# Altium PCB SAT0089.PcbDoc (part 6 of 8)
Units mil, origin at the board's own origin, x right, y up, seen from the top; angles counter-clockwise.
Board outline 4075 x 2715 mil, 6 copper layers (Top Layer, InternalPlane1, MidLayer1, Internal Plane 3, InternalPlane2, Bottom Layer), stack 67.4 mil thick; 538 components, 405 nets, 1716 pads, 1236 vias.
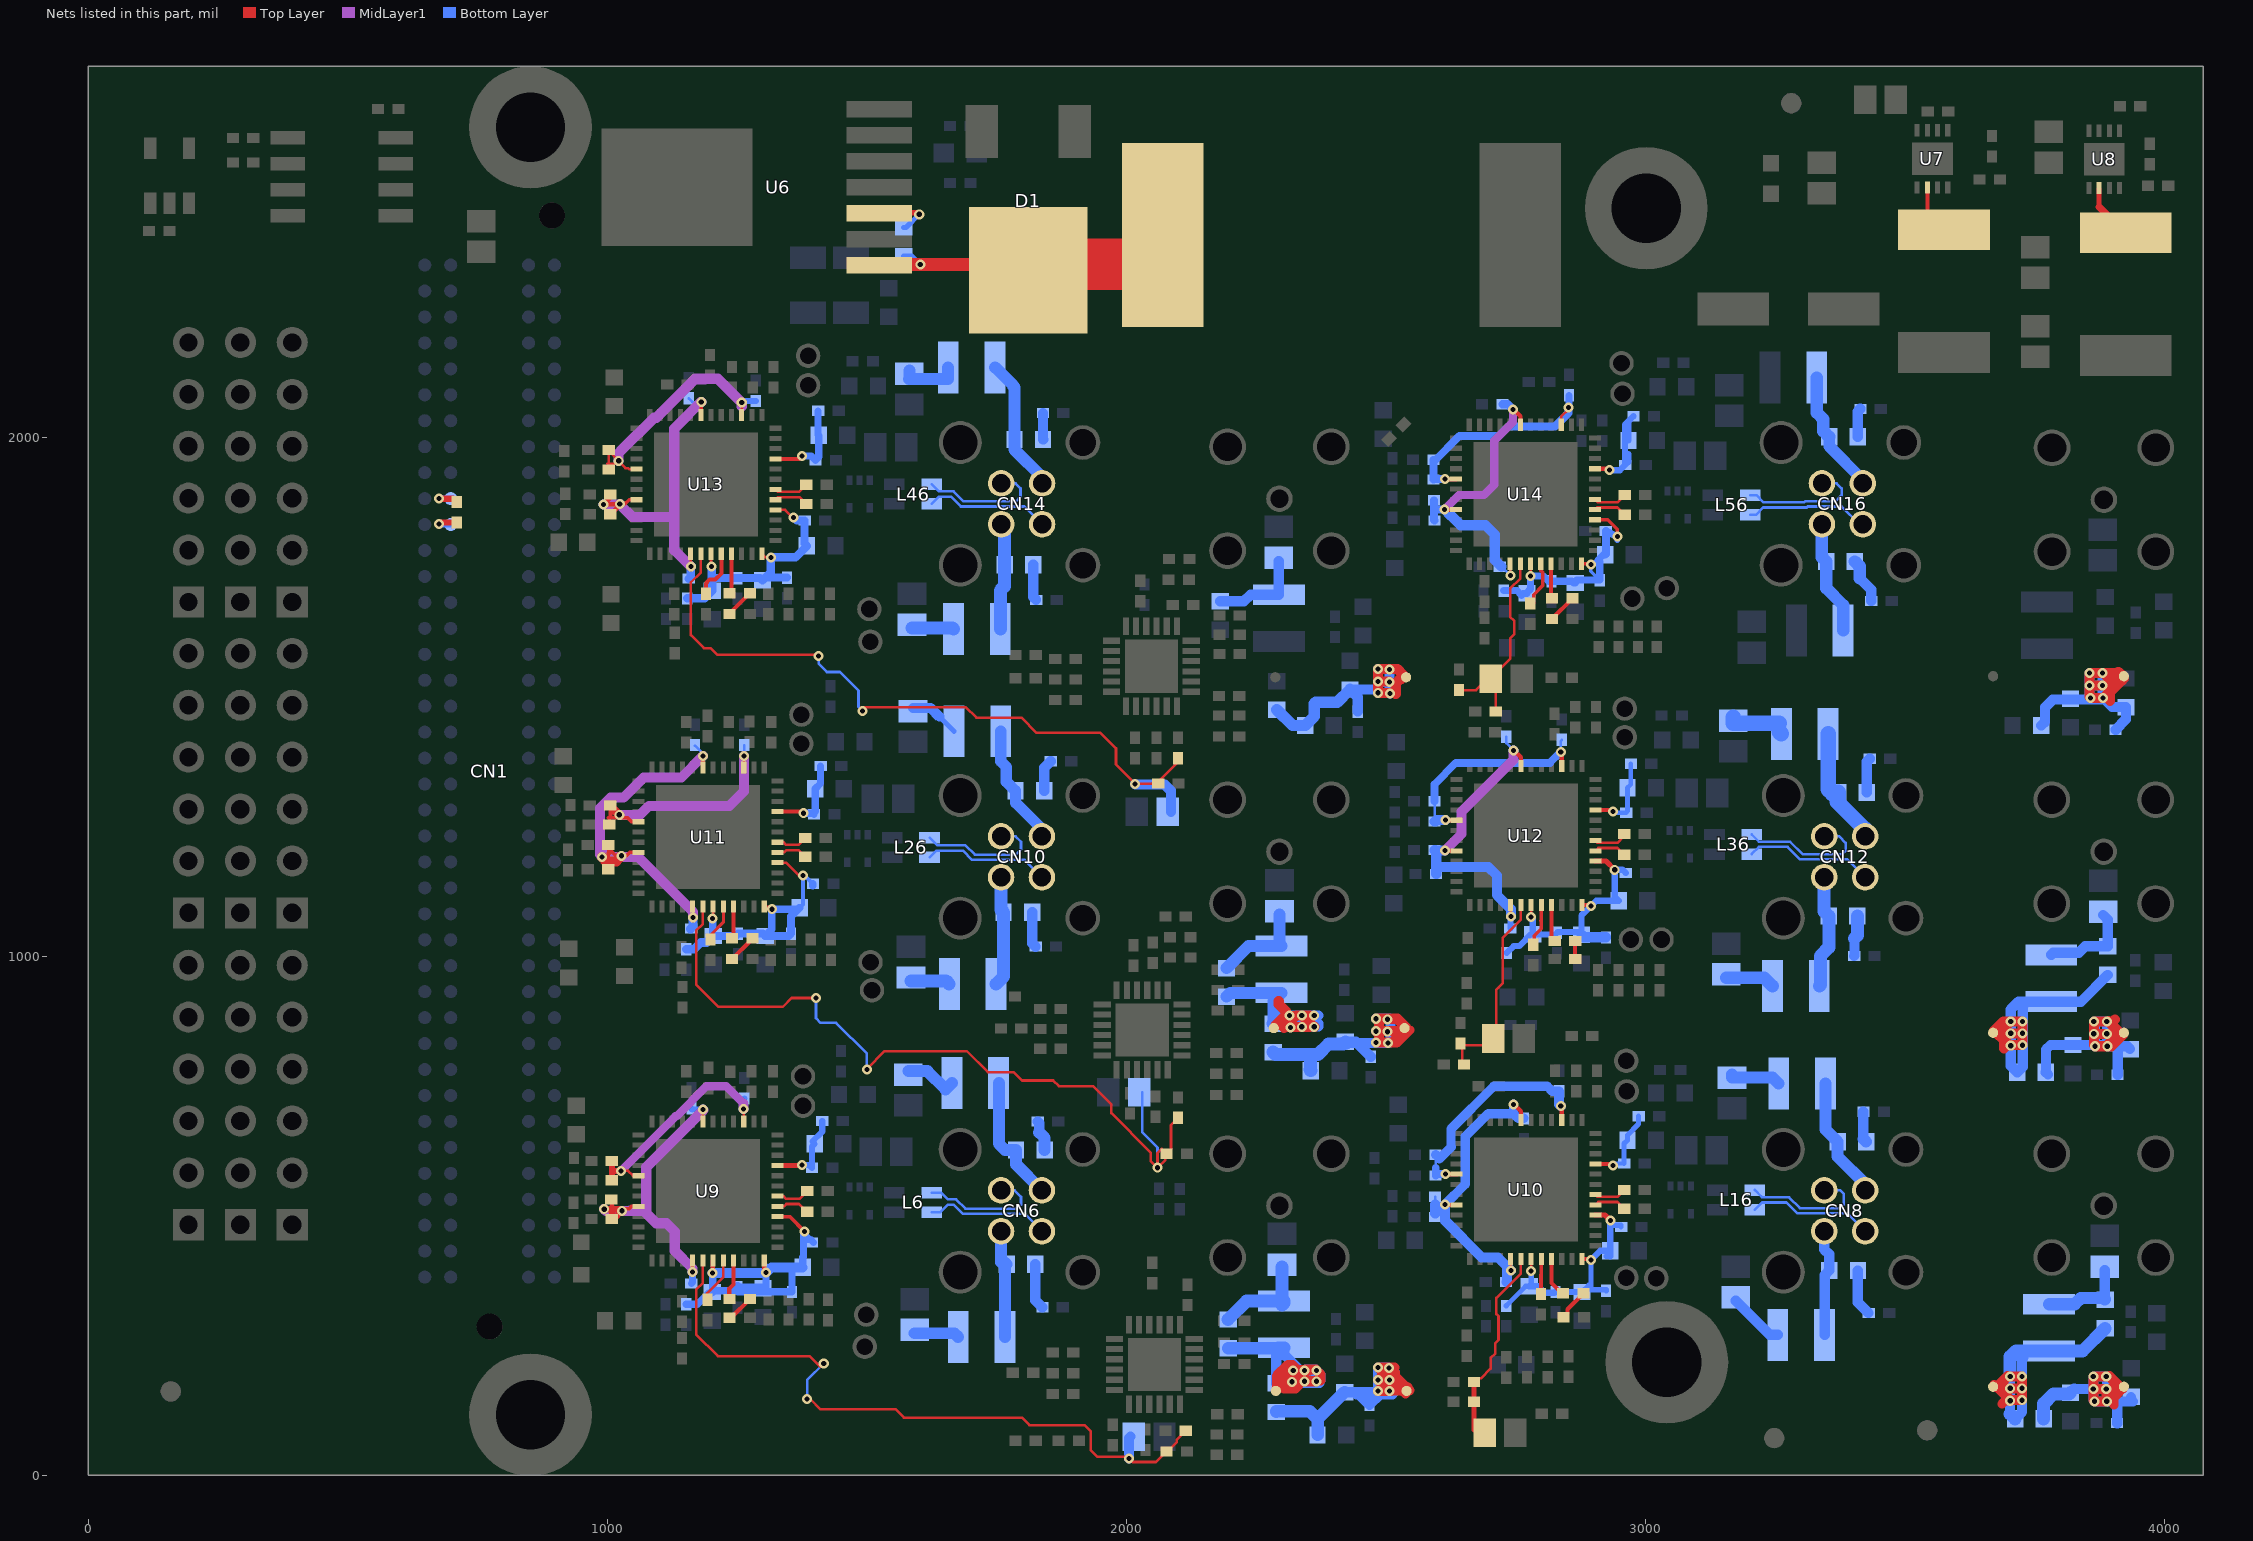
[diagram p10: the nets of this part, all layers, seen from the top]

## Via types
v1: diameter 19.29, hole 9.84, Top Layer to Bottom Layer, tented both sides, 1155 vias
v2: diameter 19.68, hole 7.87, Top Layer to Bottom Layer, tented both sides, 80 vias
v3: diameter 22, hole 10, Top Layer to Bottom Layer, tented both sides, 1 vias

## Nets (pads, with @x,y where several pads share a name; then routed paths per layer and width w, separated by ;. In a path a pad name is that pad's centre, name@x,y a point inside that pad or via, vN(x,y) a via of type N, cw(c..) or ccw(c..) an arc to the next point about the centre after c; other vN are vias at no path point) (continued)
NetC10_1: C10.1 U6.3 | length 100.8
  Top Layer w9.84: U6.3@1542,2433 1598,2433 v1(1601,2430)
  Bottom Layer w9.84: C10.1@1571,2404.5 1575.5,2404.5 v1(1601,2430)
NetC10_2: C10.2 D1.4 L1.1 U6.1 | length 590.3
  Top Layer w25: U6.1@1542,2333 v1(1603,2333) 1811.31,2333 D1.4@1812.05,2333.74
  Top Layer w50: L1.1@2013.82,2333.74 L1.1@2069.92,2389.84
  Top Layer w100: D1.4@1812.05,2333.74 L1.1@2013.82,2333.74
  Bottom Layer w9.84: C10.2@1571,2349.5 1586.5,2349.5 v1(1603,2333)
NetC16_1: C16.1 C17.1 L7.1 L9.2 R27.2 | length 900.3
  Top Layer w17.72: v1@2510,163 2533.08,163 2534.08,163 2535.11,163 L9.2@2539.98,163 2544.95,163 L9.2@2546.02,164.06
  Top Layer w19.29: v1@2498,184 2497,184 ; v1(2507,184) 2516,175 2519,175 ; v1@2510,163 v1(2507,163) ; 2517,208 v1@2507,208 ; 2519,184 2519,175 ; L9.2@2533.08,163 L9.2@2538.02,158.06 ; L9.2@2534.08,163 L9.2@2538.02,159.06 ; L9.2@2540.11,168 2518,190.11 2518,198 2515,198 v1(2506,207) ; v1(2485,184) 2494,175 2497,175 ; v1(2485,184) 2497,184 ; v1(2485,184) 2496,195 2497,195 ; 2497,175 2497,174 2496,174 v1(2485,163) v1(2507,163) ; 2497,175 2497,184 ; 2497,184 2497,195 ; 2497,195 2497,199 2494,199 v1(2485,208) v1@2506,208 ; v1(2506,207) v1@2506,208 ; v1(2506,207) v1@2507,208 ; v1@2506,208 v1@2507,208 ; v1(2507,163) 2518,174 2519,174 2519,175
  Top Layer w24: L9.2@2535.11,163 L9.2@2540.11,168
  Bottom Layer w19.29: 2464.5,160.5 v1@2487,160.5 ; 2497,156 2492,156 v1@2487.5,160.5 ; 2497,175 2494,175 v1(2485,184) ; 2497,195 2496,195 v1(2485,184) ; v1(2507,184) 2518,184 ; 2516.5,160.5 2512,160.5 v1@2509.5,160.5 ; v1(2485,184) v1(2485,163) v1@2487,161 ; v1(2485,184) v1(2485,208) 2505,208 v1(2506,207) 2515,198 2518,198 2518,184 ; v1@2487,160.5 v1@2487,161 ; v1@2487,160.5 v1@2487.5,160.5 ; v1@2487,161 v1@2487.5,160.5 ; v1@2487.5,160.5 v1@2509.5,160.5 ; v1@2509.5,160.5 2509,161 v1(2507,163) 2508,164 2518,164 2518,184
  Bottom Layer w20: L7.1@2421,160.5 2464.5,160.5 C16.1@2464.5,140 ; 2443.5,156 2448.5,156 C16.1@2464.5,140 ; 2492,156 2488.5,156 2468.5,136 C16.1@2464.5,140 ; 2497,156 2512,156 2512,160.5 2512,161 v1@2509,161
  Bottom Layer w24: R27.2@2289,122.5 2289,123.5 2353.5,123.5 2368.5,108.5 ; C17.1@2368.5,78 2368.5,108.5 ; L7.1@2421,160.5 2420.5,160.5 2368.5,108.5
NetC20_1: C20.1 CN6.3 L4.1 | length 253.4
  Bottom Layer w23: L4.1@1754.28,756 1754.28,639.22 1766.5,627 C20.1@1787.44,627 1787.5,627 1787.5,599.24 CN6.3@1837.37,549.37
NetC20_2: C20.2 R28.2 | length 60.6
  Bottom Layer w20: R28.2@1829,682 1832,679 1832,661
  Bottom Layer w23: 1832,661 1842.5,650.5 C20.2@1842.5,627
NetC21_1: C21.1 CN6.1 L5.1 | length 213.6
  Bottom Layer w23: CN6.1@1758.63,470.63 1758.63,410.87 1765.63,410.87 1769.5,407 1766.28,403.78 L5.1@1766.28,267
NetC21_2: C21.2 R29.2 | length 88.6
  Bottom Layer w20: C21.2@1824.5,407 1824.5,337.5 R29.2@1838,324
NetC23_1: C23.1 U9.41 | length 65.2
  Top Layer w5: U9.41@1327.86,518.47 1340.47,518.47 1345,523 1369,523 1384,508 C23.1@1385,508
NetC24_1: C24.1 U9.42 | length 65.5
  Top Layer w5: U9.42@1327.86,538.16 1339.51,538.16 1344.67,533 1370,533 C24.1@1385,548
NetC25_1: C25.1 U9.32 | length 88.6
  Top Layer w5: C25.1@1193,339 1192,340 1192,351 1223.53,382.53 U9.32@1223.53,414.14
NetC26_1: C26.1 R30.1 | length 53.9
  Top Layer w8: R30.1@1235.32,305 1239.68,305 C26.1@1274.68,340
NetC26_2: C26.2 U9.33 | length 77.7
  Top Layer w8: C26.2@1235.31,340 1235,340.31 1235,360 1243.21,368.21 U9.33@1243.21,414.14
NetC27_1: C27.1 C208.1 L10.1 U9.3 U9.17 | length 484
  Top Layer w5: L10.1@1009,606 1010,605 1010,587 ; v1(1026,587) 1040,587 1049.47,577.53 U9.17@1060.14,577.53 ; v1(1262,706) 1262.9,705.1 U9.3@1262.9,681.86
  Top Layer w11.81: C208.1@1009,569 L10.1@1009,606 ; 1010,587 v1(1026,587)
  MidLayer1 w16: v1(1026,587) 1131,692 1133,692 1191,750 1229,750 1262,717
  MidLayer1 w19.29: v1(1262,706) 1262,717
  Bottom Layer w11.81: v1(1262,706) 1262,724 C27.1@1264,726
NetC30_1: C30.1 C31.1 C32.1 L11.1 U9.7 U9.20 U9.29 | length 730.8
  Top Layer w5: v1(1184,705) 1184,682.02 U9.7@1184.16,681.86
  Top Layer w7.01: C31.1@1009,532 1009,516 1011,514 1042,514 1046.47,518.47 U9.20@1060.14,518.47 ; v1(1164,392) 1164.47,392.47 U9.29@1164.47,414.14
  Top Layer w12: v1(994,513) 1009,513 ; 1009,516 1009,513 ; 1009,513 1025,513 v1(1028,510) 1012,494 1009,494 1009,513
  MidLayer1 w19.29: v1(994,513) 997,510 v1(1028,510) 1044,510 ; 1130,433 1164,399 v1(1164,392) ; v1(1184,705) v1@1185,704
  MidLayer1 w19.68: 1044,510 1070,510 1094,486 1114,486 1130,470 1130,433 ; 1075,510 1075,594 v1@1185,704
  Bottom Layer w11.81: C30.1@1162,707 1164,705 v1(1184,705)
  Bottom Layer w13.78: C32.1@1162,370 1164,372 v1(1164,392)
NetC35_1: C35.1 C36.1 C37.1 C38.1 C39.1 C40.1 L12.1 U9.31 U9.36 U9.40 | length 838.1
  Top Layer w7: U9.40@1327.86,498.79 1351.21,498.79 v1(1380,470)
  Top Layer w8: v1(1203,390) 1203,413.3 U9.31@1203.84,414.14 ; U9.36@1302.27,414.14 1302.27,394.73 v1(1306,391)
  Bottom Layer w5: v1(1380,470) 1397,453 C37.1@1397,449
  Bottom Layer w13.78: L12.1@1152,330 1174,330 1195.5,351.5 1202,351.5 C40.1@1202,352.5 ; v1(1203,390) C40.1@1203,356 ; C35.1@1251,363 C35.1@1251,362.68 C35.1@1251,356 ; C39.1@1300,360.5 1300,357.5 1306,357.5 v1(1306,391) ; v1(1380,470) 1379,469 1378,469 1378,455 ; C37.1@1397,449 1391,455 1378,455 ; C40.1@1202,352.5 C40.1@1202,353.56 1202,356 C40.1@1203,356 ; C40.1@1202,352.5 1203,352.5 C40.1@1203,356 ; C40.1@1203,356 C35.1@1251,356 ; C35.1@1251,356 1251,354 1356,354 1356,397.5 1376.5,397.5 1376.5,401 1376.5,420.5 1378,420.5 1378,455
  Bottom Layer w19.29: v1(1203,390) 1305,390 v1(1306,391) 1316,401 C38.1@1376.44,401 C38.1@1376.5,401
  Bottom Layer w19.68: C35.1@1251,363 1254,360 1299.5,360 C39.1@1300,360.5
NetC43_1: C43.1 C44.1 L13.1 U9.45 | length 170.6
  Top Layer w9: U9.45@1327.86,597.21 1374.21,597.21 v1(1375,598)
  Bottom Layer w11.81: v1(1375,598) 1389,598 1394,593 1394,633.5 1399.5,639 1395,643.5 1414,662.5 L13.1@1414,683
NetC47_1: C47.1 R40.2 R47.2 U9.30 | length 1379.2
  Top Layer w5: U9.30@1184.16,414.14 1184.16,371.16 1171,358 1171,272 1213,230 1390,230 1410,210 1417,210 v1(1417,216) ; v1(1385,147) 1391,147 1410,128 1555,128 1571.5,111.5 1798.5,111.5 1813,97 1919,97 1931.5,84.5 1931.5,48.5 1944,36 2002,36 v1(2005,33) 2012,26 2057,26 2077,46 R47.2@2077.31,46 2079,46 2097,64 2097,68 R40.2@2115,86
  Bottom Layer w5: v1(1385,147) 1385,184 v1(1417,216)
  Bottom Layer w19.29: v1(2005,33) 2005,72 C47.1@2008,75
NetC48_1: C48.1 C49.1 L17.1 L19.2 R54.2 | length 702.9
  Top Layer w17.72: v1(3888,167) 3888,151 3891.06,147.94 3903,136 3903,150.05 L19.2@3920.02,167.06
  Top Layer w19.29: v1@3886.11,143 v1(3865,143) 3863,145 v1(3863,167) ; v1@3894.11,191 v1(3888,191) v1(3863,191) v1(3863,167) ; 3910.11,167 v1(3888,167) v1(3863,167)
  Top Layer w19.68: v1@3886.11,143 3891.06,147.94 3910.11,167 3914.11,171 v1@3894.11,191
  Bottom Layer w19.29: C49.1@3826.5,167 v1(3863,167) ; L17.1@3936,151.5 L17.1@3936,151.44 3936,146.5 3939.5,143 3909,143 v1(3889,143) ; v1(3863,167) v1(3888,167) v1@3889,167 ; v1(3863,167) 3863,145 v1(3865,143) v1(3889,143) ; v1(3863,167) v1(3863,191) v1(3888,191) 3889,190 v1@3889,167 ; v1(3889,143) v1@3889,167
  Bottom Layer w20: C49.1@3819,159.5 C49.1@3826.5,167 ; C48.1@3909,101 3909,143
  Bottom Layer w25: R54.2@3767.5,109 3767.5,138.5 3786,157 3816.5,157 C49.1@3819,159.5
NetC52_1: C52.1 CN8.3 L14.1 | length 237.1
  Bottom Layer w23: L14.1@3347.28,755 3347.28,666.22 3370.5,643 3370.5,614.5 3423.37,561.63 CN8.3@3423.37,549.37
NetC52_2: C52.2 R55.2 | length 60.3
  Bottom Layer w20: C52.2@3420,648.5 R55.2@3420,701
  Bottom Layer w23: C52.2@3420,648.5 C52.2@3425.5,643
NetC53_1: C53.1 CN8.1 L15.1 | length 207.5
  Bottom Layer w20: CN8.1@3344.63,470.63 3344.63,435.37 3354,426 3354,395.5 3354.5,395 3345.28,385.78 L15.1@3345.28,271
NetC53_2: C53.2 R56.2 | length 90.5
  Bottom Layer w20: C53.2@3409.5,395 3409.5,333.5 R56.2@3430,313
NetC55_1: C55.1 U10.41 | length 62.8
  Top Layer w5: U10.41@2903.86,521.47 2909.39,527 2946,527 C55.1@2959,514
NetC56_1: C56.1 U10.42 | length 62.2
  Top Layer w5: U10.42@2903.86,541.16 2908.02,537 2946,537 C56.1@2959,550
NetC57_1: C57.1 U10.32 | length 67.4
  Top Layer w7: C57.1@2799,350 2799,386.47 2799.53,387 U10.32@2799.53,417.14
NetC58_1: C58.1 R57.1 | length 61.9
  Top Layer w8: R57.1@2842.32,305 2850,312.68 2850,320.32 C58.1@2880.68,351
NetC58_2: C58.2 U10.33 | length 75.8
  Top Layer w8: U10.33@2819.21,417.14 2819.21,370.79 C58.2@2840,350
NetC59_1: C59.1 C209.1 L20.1 U10.3 U10.17 | length 464.8
  Top Layer w8: v1(2615,581) 2615.47,580.53 U10.17@2636.14,580.53 ; v1(2837,712) 2837,710.1 2838.9,710.1 U10.3@2838.9,684.86
  Bottom Layer w5: 2596,593 L20.1@2596,618
  Bottom Layer w15: 2596,593 2596,578 2599,581 v1(2615,581)
  Bottom Layer w18: L20.1@2596,618 2603,611 2603,610 2626,633 2625.5,633.5 2625.5,667.5 2708,750 2811,750 2821,740 C209.1@2834,740
  Bottom Layer w19.29: C209.1@2834,740 2834,715 v1(2837,712)
NetC62_1: C62.1 C63.1 C64.1 L21.1 U10.7 U10.20 U10.29 | length 731.6
  Top Layer w5: U10.29@2740.47,417.14 2740.47,395.53 v1(2741,395)
  Top Layer w8: v1(2614,522) 2614.53,521.47 U10.20@2636.14,521.47 ; v1(2746,715) 2747,715 2760.16,701.84 U10.7@2760.16,684.86
  MidLayer1 w5: v1@2741,390 v1(2741,395)
  Bottom Layer w5: L21.1@2595,498 2595,505 2597,505 v1(2614,522) 2595,522 C64.1@2595,537 ; C62.1@2732,373 2732,386 2733.5,387.5 v1(2741,395)
  Bottom Layer w18: v1(2614,522) 2653,561 2653,653 2697,697 2746,697 ; v1(2746,715) 2746,697 ; C63.1@2766,688 2755,688 2746,697
  Bottom Layer w19.29: 2614,491 v1(2614,522) ; 2716,420 2733.5,402.5 ; C62.1@2732,373 2733.5,374.5 2733.5,387.5 v1@2733.5,395 ; v1@2733.5,395 v1(2741,395) 2733.5,402.5 ; v1@2733.5,395 2733.5,402.5
  Bottom Layer w20: L21.1@2595,505 2595,522 ; 2614,491 2685,420 2716,420
NetC67_1: C67.1 C68.1 C69.1 C70.1 C71.1 C72.1 L22.1 U10.31 U10.36 U10.40 | length 539.9
  Top Layer w5: U10.31@2779.84,417.14 2779.84,394.16 v1(2780,394)
  Top Layer w8: U10.36@2878.27,417.14 2892.86,417.14 v1(2895,415)
  Top Layer w9.84: U10.40@2903.86,501.79 2922.21,501.79
  Top Layer w10: 2922.21,501.79 v1(2933,491)
  Bottom Layer w10: L22.1@2732,327 2769.5,364.5 2776,364.5 2780,368.5 v1(2780,394) ; C70.1@2878,353.5 2891,366.5 2895,366.5 ; v1(2895,415) 2895,366.5 ; C68.1@2924,356 2925,356 2925,358 2895,358 2895,366.5 ; C72.1@2924,422.5 C72.1@2932.5,422.5 ; v1(2933,491) 2933,482 2953,482 C67.1@2953,479
  Bottom Layer w12: C71.1@2776,364.5 2793.5,364.5 2806,352 2825,352 2827,354 2827.5,353.5 C70.1@2878,353.5 ; v1(2895,415) 2913,433 C72.1@2932.44,433 C72.1@2932.5,433 ; C72.1@2932.5,422.5 C72.1@2932.5,433 ; v1(2933,491) 2932.5,490.5 C72.1@2932.5,433
NetC75_1: C75.1 R69.2 R170.2 U10.30 | length 422.9
  Top Layer w5: R69.2@2670,180 2676,186 2676,187 2683,187 2702,206 2702,226 2711,235 2711,255 2717,261 2717,307 2713,311 2713,342 2760.16,389.16 U10.30@2760.16,417.14
  Top Layer w10: R69.2@2670,180 2670,88 2684,88 C75.1@2684,68 ; C75.1@2676,68 C75.1@2684,68 ; C75.1@2691,68 C75.1@2684,68
NetC76_1: C76.1 C79.1 L23.1 U10.45 | length 167.2
  Top Layer w8: U10.45@2903.86,600.21 v1@2934.79,600.21 ; v1@2934.79,600.21 v1(2938,597) 2938,600.21 v1@2934.79,600.21
  Bottom Layer w8: v1(2938,597) 2942,601 C79.1@2959,601
  Bottom Layer w10: C79.1@2959,601 2959,639.5 2965.5,646 2965.5,655.5 2987,677 L23.1@2987,692
NetC80_1: C80.1 C81.1 L27.1 L29.2 R78.2 | length 889.7
  Top Layer w8: v1(2503,855) 2533.11,855 2542.95,855 2546.02,858.06
  Top Layer w17.72: v1(2504,833) 2520.95,833 2540.02,852.06 2542.95,855 2546.02,858.06
  Top Layer w19.29: v1(2503,855) v1@2504,856 ; v1(2503,879) v1@2504,880 ; L29.2@2534.02,858.06 L29.2@2531.95,856 ; v1(2481,856) 2487,850 v1@2487,840 ; v1(2481,856) v1@2487,862 ; v1(2481,856) v1@2487,856 ; v1@2487,834 v1(2481,834) v1@2487,840 ; v1@2487,834 v1@2487,840 ; v1@2487,834 2512.11,834 2533.11,855 L29.2@2534.11,856 ; v1@2487,856 v1@2487,862 ; v1@2487,856 v1@2504,856 ; v1@2487,862 2487,874 v1(2481,880) v1@2504,880 ; v1@2504,856 L29.2@2531.95,856 ; v1@2504,880 2522.11,880 2540.11,862 L29.2@2534.11,856 ; L29.2@2531.95,856 L29.2@2534.11,856
  Bottom Layer w19.29: L27.1@2424.5,833 2445,833 v1@2482,833 ; v1@2508,856 v1@2504,856 ; v1@2508,880 v1@2504,880 ; v1(2481,834) 2487,834 v1@2487,840 ; v1(2481,834) v1@2487,840 ; v1(2481,834) v1@2482,833 ; v1(2481,856) v1@2487,856 ; v1(2481,856) 2487,850 v1@2487,840 ; v1(2481,856) v1@2487,862 ; v1@2482,833 v1(2504,833) 2505,834 2509,834 2509,849 v1(2503,855) ; v1@2487,856 v1@2487,862 ; v1@2487,856 v1@2504,856 ; v1@2487,862 2487,874 v1(2481,880) v1@2504,880 ; v1(2503,855) 2509,855 v1@2509,861 ; v1(2503,855) v1@2504,856 ; v1@2504,856 v1@2509,861 ; v1@2504,880 v1(2503,879) 2509,873 v1@2509,861
  Bottom Layer w20: L27.1@2422,835.5 2442.5,835.5 2445,833 C80.1@2471,807
  Bottom Layer w25: R78.2@2283,815.5 2287,811.5 2355,811.5 ; C81.1@2353.5,782 C81.1@2355,780.5 ; C81.1@2355.5,780 C81.1@2355,780.5 ; L27.1@2424.5,833 2422,835.5 2418,831.5 2389.5,831.5 2369.5,811.5 2355,811.5 ; C81.1@2355,780.5 2355,811.5
NetC84_1: C84.1 CN10.3 L24.1 | length 235.4
  Bottom Layer w22: L24.1@1758.28,1434 1758.28,1375.72 1769,1365 1769,1336.5 1786.5,1319 1786.5,1296.5 1837.37,1245.63 CN10.3@1837.37,1231.37
NetC84_2: C84.2 R79.2 | length 62.2
  Bottom Layer w20: C84.2@1841.5,1319 1841.5,1363.5 R79.2@1854,1376
NetC85_1: C85.1 CN10.1 L25.1 | length 213.5
  Bottom Layer w25: L25.1@1749.28,947 1763.5,961.22 1763.5,1085 1758.63,1089.87 CN10.1@1758.63,1152.63
NetC85_2: C85.2 R80.2 | length 68.7
  Bottom Layer w20: C85.2@1818.5,1085 1818.5,1025.5 R80.2@1825,1019
NetC87_1: C87.1 U11.41 | length 60.4
  Top Layer w5: U11.41@1327.86,1200.47 1340.47,1200.47 1345,1205 1368,1205 C87.1@1381,1192
NetC88_1: C88.1 U11.42 | length 60.7
  Top Layer w5: U11.42@1327.86,1220.16 1339.51,1220.16 1344.67,1215 1368,1215 C88.1@1381,1228
NetC89_1: C89.1 U11.32 | length 73.3
  Top Layer w6: C89.1@1199,1033 1199,1041.47 1223.53,1066 U11.32@1223.53,1096.14
NetC90_1: C90.1 R81.1 | length 53.9
  Top Layer w8: R81.1@1240.32,995 1275.32,1030 C90.1@1279.68,1030
NetC90_2: C90.2 U11.33 | length 62.3
  Top Layer w8: C90.2@1240.31,1035 1243.21,1037.9 U11.33@1243.21,1096.14
NetC91_1: C91.1 C210.1 L30.1 U11.3 U11.17 | length 492.5
  Top Layer w5: U11.3@1262.9,1363.86 1262.9,1385.9 v1(1263,1386)
  Top Layer w7: 1002,1267 1004,1267 ; C210.1@1004,1254 1004,1267 ; L30.1@1006,1291 1006,1290 1006,1267 ; U11.17@1060.14,1259.53 1046.47,1259.53 1039,1267 1006,1267 ; 1004,1267 1006,1267
  Top Layer w16: L30.1@1006,1290 v1(1023,1273)
  MidLayer1 w19.29: v1(1023,1273) 1063,1273 1080,1290 1235,1290 1263,1318 v1(1263,1386)
  Bottom Layer w5: v1(1263,1386) 1264,1387 C91.1@1264,1407
NetC94_1: C94.1 C95.1 C96.1 L31.1 U11.7 U11.20 U11.29 | length 954.2
  Top Layer w5: L31.1@1002,1168 989,1181 989,1191 v1(990,1192) 990,1183 v1@991,1184 ; C96.1@1002,1215 1002,1203 1003.5,1201.5 1006,1199 1002,1195 994.5,1187.5 v1@991,1184 ; 1018,1185 1017,1184 1002,1184 998,1184 v1@991,1184 ; U11.29@1164.47,1096.14 1164.47,1075 v1(1165,1075)
  Top Layer w7: L31.1@1002,1168 1002,1183 1002,1184 1002,1195 1002,1200 1003.5,1201.5 1005,1203 1004,1204 ; C96.1@1002,1215 1004,1213 1004,1204 ; U11.20@1060.14,1200.47 1043.47,1200.47 1037,1194 v1(1027,1194) 1021,1194 1020,1193 1017,1193 1006,1204 1004,1204
  Top Layer w7.87: v1(1184,1386) 1184,1364.02 U11.7@1184.16,1363.86
  Top Layer w19.29: v1(990,1192) 994.5,1187.5 998,1184 999,1183 1002,1183 1018,1183 1018,1185 v1(1027,1194)
  MidLayer1 w19.29: v1(1027,1194) v1@1027,1192 ; v1(1165,1075) 1165,1086 1059,1192 v1@1027,1192 ; v1(1184,1386) 1143,1345 1070,1345 1031,1306 1006,1306 986,1286 986,1211 ; 986,1211 986,1196 v1(990,1192) 1005,1192 ; 986,1211 1005,1192 ; 1005,1192 v1@1027,1192
  Bottom Layer w5: C94.1@1169,1406 1184,1391 v1(1184,1386)
  Bottom Layer w17: C95.1@1160,1053 1165,1058 v1(1165,1075)
NetC99_1: C99.1 C100.1 C101.1 C102.1 C103.1 C104.1 L32.1 U11.31 U11.36 U11.40 | length 609.9
  Top Layer w5: v1(1203,1073) 1203.84,1073.84 U11.31@1203.84,1096.14 ; U11.36@1302.27,1096.14 1311.86,1096.14 v1(1317,1091) ; U11.40@1327.86,1180.79 1344.21,1180.79 1369,1156 v1(1377,1156)
  Bottom Layer w7.87: C102.1@1370.5,1094 1377,1100.5 v1(1377,1156) 1380,1156 C100.1@1396,1140
  Bottom Layer w15: v1(1203,1073) 1203,1040.5 1204,1039.5 1247.5,1039.5 1252,1044 1299.5,1044 C103.1@1304,1039.5 ; C102.1@1370.5,1094 C102.1@1367.5,1091 ; C100.1@1396,1136.5 C100.1@1396,1140 ; C103.1@1304,1039.5 1349.5,1039.5 1354,1044 1354,1077.5 C102.1@1367.5,1091 ; C103.1@1304,1039.5 1317,1052.5 v1(1317,1091) C102.1@1367.5,1091
  Bottom Layer w17: L32.1@1152,1014 1167,1014 1180,1027 1191.5,1027 C104.1@1204,1039.5
NetC107_1: C107.1 R93.2 R173.2 U11.30 | length 1617.8
  Top Layer w5: U11.30@1184.16,1096.14 1184.16,1063 1171,1049.84 1171,946 1214,903 1338,903 1355,920 v1(1402,920) ; v1(1500,782) 1500,783.5 1534,817.5 1692.5,817.5 1733,777 1783,777 1799,761 1859,761 1870,750 1936,750 1971,715 1971,698 2047,622 2047,606 v1(2060,593) ; R173.2@2099.45,688.74 2086,675.29 2086,629 2077,620 R93.2@2075,622 ; v1(2060,593) 2075,608 R93.2@2075,622 ; v1(2060,593) 2060,621 2068,629 R93.2@2075,622
  Bottom Layer w5: v1(1402,920) 1402,881 1411,872 1441,872 1500,813 v1(1500,782) ; C107.1@2031,738 2031,661 2060,632 v1(2060,593)
NetC108_1: C108.1 C111.1 L33.1 U11.45 | length 171.3
  Top Layer w8: U11.45@1327.86,1279.21 1374.79,1279.21 v1(1378,1276)
  Bottom Layer w13.78: v1(1378,1276) C111.1@1398,1276 ; C111.1@1398,1274 C111.1@1398,1276 ; L33.1@1411,1367 1411,1333.5 1400.5,1323 1400.5,1279.5 1398,1279.5 C111.1@1398,1276
NetC112_1: C112.1 C114.1 L37.1 L38.2 R102.2 | length 698.9
  Top Layer w19.29: v1@3888.11,827 v1(3866,827) 3864,829 v1(3864,851) ; v1(3890,827) 3897.95,827 3920.02,849.06 3918.08,851 3912.11,851 ; 3905,879 3901,875 3892.11,875 v1(3889,875) v1(3864,875) v1(3864,851) ; L38.2@3914.11,853 3912.11,851 ; v1(3864,851) v1(3889,851) 3912.11,851
  Top Layer w19.68: v1@3888.11,827 3912.11,851 ; v1@3892.11,875 L38.2@3914.11,853
  Bottom Layer w19.29: C114.1@3824,829.5 v1@3866,829.5 ; v1(3864,851) v1@3866,851 ; v1(3866,827) v1@3866,829.5 ; L37.1@3928.5,827 3907,827 v1(3890,827) v1@3889,828 ; v1@3866,829.5 v1@3866,851 ; v1@3866,829.5 3887.5,829.5 v1@3889,828 ; v1@3866,851 v1(3889,851) ; v1@3866,851 3866,873 v1(3864,875) v1(3889,875) v1(3889,851) ; v1@3889,828 v1(3889,851)
  Bottom Layer w19.68: R102.2@3776,772.5 3771.5,777 3772,777.5 3772,821 3780.5,829.5 C114.1@3824,829.5 ; 3907,827 3910,824 C112.1@3910,772 ; L37.1@3928.5,827 L37.1@3934,821.5
NetC116_1: C116.1 CN12.3 L34.2 | length 238
  Bottom Layer w30: L34.2@3352.28,1429 3352.28,1322.22 3360.5,1314 3362.5,1316 C116.1@3371.44,1316 3371.5,1316 3371.5,1300.5 3369.5,1298.5 3423.37,1244.63 CN12.3@3423.37,1231.37
NetC116_2: C116.2 R103.2 | length 67.3
  Bottom Layer w20: C116.2@3426.5,1316 3426.5,1375.5 R103.2@3432,1381
NetC117_1: C117.1 CN12.1 L35.2 | length 220.9
  Bottom Layer w25: L35.2@3335.28,943 3337,944.72 3337,1001 3353.5,1017.5 3353.5,1078 3344.63,1086.87 CN12.1@3344.63,1152.63
NetC117_2: C117.2 R104.2 | length 79.7
  Bottom Layer w20: R104.2@3402,1001 3403,1002 3403,1035
  Bottom Layer w25: 3403,1035 3408.5,1040.5 C117.2@3408.5,1078
NetC119_1: C119.1 U12.41 | length 62.8
  Top Layer w5: U12.41@2903.86,1203.47 2909.39,1209 2946,1209 C119.1@2959,1196
NetC120_1: C120.1 U12.42 | length 66.2
  Top Layer w5: U12.42@2903.86,1223.16 2908.02,1219 2946,1219 2959,1232 C120.1@2959,1236
NetC121_1: C121.1 U12.32 | length 83.3
  Top Layer w7: C121.1@2784,1023 2786,1025 2786,1040 2799.53,1053.53 2799.53,1069 ; 2799,1068.47 2799.53,1069 ; U12.32@2799.53,1099.14 2799.53,1069
NetC122_1: C122.1 U12.33 | length 71.7
  Top Layer w8: U12.33@2819.21,1099.14 2819.21,1036.1 C122.1@2825.32,1030
NetC122_2: C122.2 R105.1 | length 35
  Top Layer w8: R105.1@2864.68,995 C122.2@2864.69,1030
NetC123_1: C123.1 C125.1 C130.1 C131.1 C135.1 C138.1 L41.1 U12.31 U12.36 U12.40 | length 538.4
  Top Layer w5: U12.31@2779.84,1099.14 2779.84,1076.16 v1(2780,1076)
  Top Layer w8: U12.36@2878.27,1099.14 2892.86,1099.14 v1(2895,1097)
  Top Layer w9.84: U12.40@2903.86,1183.79 2924.21,1183.79 v1(2941,1167)
  Bottom Layer w12: L41.1@2733,1007 2746,1020 2757,1020 2779.5,1042.5 C125.1@2783,1042.5 ; v1(2780,1076) 2783,1073 C125.1@2783,1042.56 C125.1@2783,1042.5 ; C130.1@2962,1161 2956,1167 v1(2941,1167) 2941,1114.97 2948.56,1107.41 C135.1@2948.5,1107.41 2905.41,1107.41 v1(2895,1097) 2877,1079 C138.1@2877,1041.56 2877,1041.5 2871.5,1047 2831,1047 2826.5,1042.5 C125.1@2783,1042.5
  Bottom Layer w20: C138.1@2877,1041.5 2881.5,1037 C123.1@2924,1037
NetC126_1: C126.1 C141.1 C142.1 L42.1 U12.7 U12.20 U12.29 | length 663.8
  Top Layer w5: U12.29@2740.47,1099.14 2740.47,1077.53 v1(2741,1077)
  Top Layer w8: v1(2614,1204) 2614.53,1203.47 U12.20@2636.14,1203.47 ; v1(2746,1397) 2747,1397 2760.16,1383.84 U12.7@2760.16,1366.86
  MidLayer1 w19.29: v1(2614,1204) 2646,1236 2646,1279 2746,1379 v1(2746,1397)
  Bottom Layer w5: C126.1@2732,1423 2732,1411 v1(2746,1397)
  Bottom Layer w12: C141.1@2740,1054 2740,1076 v1(2741,1077)
  Bottom Layer w19.29: C142.1@2596,1204 v1(2614,1204) ; 2597,1172 2698,1172 2714,1156 2714,1118 2741,1091 v1(2741,1077)
  Bottom Layer w20: C142.1@2594,1205 2595,1205 2596,1204 2597,1203 2597,1172 L42.1@2597,1159
NetC128_1: C128.1 C129.1 L43.1 U12.45 | length 165.6
  Top Layer w8: U12.45@2903.86,1282.21 v1@2934.79,1282.21 ; v1@2934.79,1282.21 v1(2938,1279) 2938,1282.21 v1@2934.79,1282.21
  Bottom Layer w9: v1(2938,1279) 2940,1277 2963,1277 2965.5,1279.5 2965.5,1325 2971.81,1331.31 L43.1@2971.81,1371.19
NetC133_1: C133.1 C211.1 L40.1 U12.3 U12.17 | length 437.1
  Top Layer w8: v1(2615,1263) 2615.47,1262.53 U12.17@2636.14,1262.53 ; v1(2837,1394) 2837,1392.1 2838.9,1392.1 U12.3@2838.9,1366.86
  Bottom Layer w5: C211.1@2594,1260 L40.1@2594,1299 ; v1(2837,1394) 2837,1415 C133.1@2839,1417
  Bottom Layer w15: L40.1@2594,1299 2594,1332 2635,1373 2816,1373 v1(2837,1394)
  Bottom Layer w19.29: C211.1@2594,1260 2596,1260 2599,1263 v1(2615,1263)
NetC139_1: C139.1 R117.2 R176.2 U12.30 | length 383.3
  Top Layer w5: R117.2@2644,832 R117.2@2647,829 ; R176.2@2651,792 2647,796 R117.2@2647,829 ; U12.30@2760.16,1099.14 2760.16,1071.16 2725,1036 2725,948 2713,936 2713,855 2687,829 R117.2@2647,829
NetC144_1: C144.1 C145.1 L47.1 L49.2 R126.2 | length 731.4
  Top Layer w5: v1@2507,1530 2523.07,1530 2532.91,1530 ; 2532.95,1530 L49.2@2537.02,1534.06
  Top Layer w8: v1(2507,1529) 2522.07,1529 2531.91,1529 2532.91,1530 L49.2@2540.39,1537.48
  Top Layer w19.29: v1(2507,1529) 2507,1530 v1(2485,1530) ; v1(2507,1553) v1@2507,1554 ; v1@2517,1508 v1(2485,1508) v1(2485,1530) ; 2521.91,1554 v1@2507,1554 ; v1(2485,1530) v1(2485,1554) v1@2507,1554
  Top Layer w19.68: v1@2517,1508 2519,1506 2519,1525.93 2522.07,1529 2523.07,1530 2534.49,1541.42 2521.91,1554
  Bottom Layer w19.29: L47.1@2431,1514.5 2478.5,1514.5 v1(2485,1508) ; v1(2508,1507) v1@2507,1508 ; v1(2485,1508) v1(2485,1530) ; v1(2485,1508) v1@2507,1508 ; v1(2485,1530) 2486,1529 v1(2507,1529) ; v1(2485,1530) v1(2485,1554) 2506,1554 v1(2507,1553) v1(2507,1529) ; v1@2507,1508 v1(2507,1529)
  Bottom Layer w20: L47.1@2431,1514.5 2446,1499.5 C144.1@2446,1472
  Bottom Layer w22: R126.2@2290,1475.5 2320.5,1445 C145.1@2344.44,1445 2344.5,1445 2362,1462.5 2362,1487 2365,1490 2406.5,1490 L47.1@2431,1514.5
NetC148_1: C148.1 CN14.3 L44.2 | length 260.9
  Bottom Layer w23: L44.2@1747.28,2135 1782,2100.28 1782,2099 1784.5,2096.5 1784.5,1976.5 1837.64,1923.36 CN14.3@1837.64,1911.5
NetC148_2: C148.2 R127.2 | length 51.1
  Bottom Layer w20: R127.2@1839.31,2047 1839.31,1996.24 C148.2@1839.56,1996
NetC149_1: C149.1 CN14.1 L45.2 | length 279.3
  Bottom Layer w5: CN14.1@1758.9,1832.76 1765,1826.65 1765.5,1826.15 C149.1@1765.5,1755
  Bottom Layer w25: L45.2@1757.28,1631 1757.28,1705.28 1765,1713 CN14.1@1765,1826.65
NetC149_2: C149.2 R128.2 | length 70.3
  Bottom Layer w20: C149.2@1820.5,1755 1820.5,1692.5 R128.2@1826,1687
NetC151_1: C151.1 U13.41 | length 66.6
  Top Layer w5: U13.41@1323.86,1880 1328.86,1885 1370,1885 C151.1@1383,1872
NetC152_1: C152.1 U13.42 | length 66.9
  Top Layer w5: U13.42@1323.86,1899.68 1328.54,1895 1369,1895 C152.1@1383,1909
NetC153_1: C153.1 U13.32 | length 95.5
  Top Layer w8: C153.1@1190,1699.21 1190,1719 1197,1726 1208,1726 1220,1738 1220,1775.2 U13.32@1219.53,1775.67
NetC154_1: C154.1 R129.1 | length 56.3
  Top Layer w8: R129.1@1235.32,1660 1235.32,1660.63 C154.1@1274.68,1700
NetC154_2: C154.2 U13.33 | length 77.3
  Top Layer w8: C154.2@1235.31,1700 1239.21,1703.9 U13.33@1239.21,1775.67
NetC155_1: C155.1 C212.1 L50.1 U13.3 U13.17 | length 560.4
  Top Layer w5: 1000,1949 1003,1949 ; L50.1@1003,1976 L50.1@1003,1974 ; U13.17@1056.14,1939.06 1041.94,1939.06 1040,1941 1035,1941 1027,1949 1014,1949 ; U13.3@1258.9,2043.39 1259,2043.49 v1(1259,2067) ; 1003,1949 L50.1@1003,1974 ; 1003,1949 1014,1949 ; 1003,1949 1003,1938 1014,1949 ; L50.1@1003,1974 v1(1022,1955) 1020,1955 1014,1949
  MidLayer1 w19.29: v1(1022,1955) 1022,1970 1027,1975
  MidLayer1 w20: 1027,1975 1090,2038 1094,2038 1168,2112 ; 1188,2112 1168,2112 ; v1@1259,2060 v1(1259,2067) 1213,2113 1169,2113 1168,2112
  Bottom Layer w12: v1(1259,2067) 1262,2070 C212.1@1286,2070
NetC158_1: C158.1 C159.1 C160.1 L51.1 U13.7 U13.20 U13.29 | length 719.9
  Top Layer w5: U13.29@1160.47,1775.67 1160.47,1751.53 v1(1161,1751)
  Top Layer w6: U13.7@1180.16,2043.39 1181,2044.23 v1(1181,2068)
  Top Layer w7: v1(1024,1872) 1034,1872 1042,1880 U13.20@1056.14,1880
  Top Layer w9: L51.1@1007,1852 1024,1869 v1(1024,1872) 1023,1871 v1(993,1871) 1007,1885 C160.1@1007,1890
  MidLayer1 w19.29: v1(993,1871) v1@1024,1871 ; v1(1024,1872) v1@1024,1871 ; 1128,1847 1048,1847 v1@1024,1871 ; 1129,1783 v1(1161,1751) ; 1156,2044 1180,2068 v1(1181,2068)
  MidLayer1 w20: 1128,1847 1129,1846 ; 1129,1783 1129,1846 ; 1156,2044 1129,2017 1129,1846
  Bottom Layer w5: C158.1@1157,2075 1164,2068 v1(1181,2068)
  Bottom Layer w16: C159.1@1157,1728 1161,1732 v1(1161,1751)
NetC163_1: C163.1 C164.1 C165.1 C166.1 C167.1 C168.1 L52.1 U13.31 U13.36 U13.40 | length 534
  Top Layer w5: U13.31@1199.84,1775.67 1199.84,1752.16 v1(1201,1751) ; U13.36@1298.27,1775.67 1304.94,1769 v1(1315,1769) ; U13.40@1323.86,1860.31 1342.68,1860.32 1357,1846 v1(1359,1846)
  Bottom Layer w16: L52.1@1154,1690 1187.5,1690 1202,1704.5 C166.1@1202,1704.56 1202,1723.5 1203,1724.5 1201,1726.5 ; v1(1201,1751) 1201,1726.5 ; C164.1@1346,1730 C168.1@1304.5,1730 ; v1(1359,1846) 1365,1840 1380,1840 1380,1795.5 1384.5,1791 1362.5,1769 v1(1315,1769) 1315,1740.5 C168.1@1304.5,1730 ; 1201,1726.5 1203.5,1729 1294.5,1729 1299,1724.5 C168.1@1304.5,1730
NetC171_1: C171.1 R141.2 R179.2 U13.30 | length 1426.3
  Top Layer w5: U13.30@1180.16,1775.67 1180.16,1740.16 1161,1721 1161,1619 1186,1594 1199,1594 1211.5,1581.5 1404.5,1581.5 v1(1407,1579) ; v1(1492,1473) 1490.5,1474.5 1490.5,1480.5 1690.5,1480.5 1711,1460 1798,1460 1827,1431 1950,1431 1980,1401 1980,1370 2017,1333 v1(2017,1332) 2018,1333 2049,1333 2055,1339 2061,1333 2061,1336 2099.45,1374.45 R179.2@2099.45,1381.65
  Bottom Layer w5: v1(1407,1579) 1407,1564 1423,1548 1448,1548 1484,1512 1484,1481 v1(1492,1473)
  Bottom Layer w19.29: v1(2017,1332) 2018,1331 2074,1331
  Bottom Layer w20: 2074,1331 2086,1319 C171.1@2086,1279
NetC172_1: C172.1 C175.1 L53.1 U13.45 | length 181.1
  Top Layer w8: U13.45@1323.86,1958.74 1369.74,1958.74 v1(1375,1964)
  Bottom Layer w13.78: v1(1375,1964) 1393,1964 1401,1956 1407.5,1962.5 1407.5,2004 1406.22,2005.28 L53.1@1406.22,2051.26
NetC176_1: C176.1 C177.1 L57.1 L59.2 R150.2 | length 857.1
  Top Layer w17.72: v1(3881,1546) 3890.94,1536.06 3898,1529 3898,1522 3898,1514 3898,1511.05 3921.52,1534.56 L59.2@3923.02,1536.06
  Top Layer w19.29: 3890.94,1536.06 L59.2@3913.17,1536.06 ; 3898,1511.05 3895,1508.05 3895,1492 3894,1493 3894,1510 ; 3911.11,1546 v1(3881,1546) v1(3856,1546) v1(3856,1522) ; L59.2@3917.11,1533.11 3898,1514 3894,1510 ; L59.2@3917.11,1540 L59.2@3913.17,1536.06 ; L59.2@3920.02,1536.06 3917.11,1536.06 L59.2@3913.17,1536.06 ; v1(3856,1522) 3856,1500 v1(3858,1498) v1(3882,1498) 3894,1510 ; v1(3856,1522) v1(3881,1522) 3898,1522 3899.11,1522 L59.2@3913.17,1536.06
  Top Layer w24: 3911.11,1546 3917.11,1540 3917.11,1536.06 L59.2@3917.11,1533.11
  Bottom Layer w5: C177.1@3819,1496.5 3856.5,1496.5 v1(3858,1498)
  Bottom Layer w19.29: 3847,1495 v1@3858,1495 ; L57.1@3926,1480.5 3899.5,1480.5 v1(3882,1498) ; v1(3856,1522) v1(3881,1522) ; v1(3856,1522) 3856,1500 v1(3858,1498) v1@3858,1495 ; v1(3856,1522) v1(3856,1546) v1(3881,1546) v1(3881,1522) ; v1@3858,1495 3879,1495 v1(3882,1498) ; v1(3881,1522) 3881,1499 v1(3882,1498)
  Bottom Layer w20: R150.2@3762.5,1445 3770,1452.5 3770,1480 3785,1495 3847,1495 ; C176.1@3906,1437 3926,1457 L57.1@3926,1480.44 L57.1@3926,1480.5
NetC180_1: C180.1 CN16.3 L54.2 | length 240.5
  Bottom Layer w22.05: C180.1@3354.07,2001.11 3354.07,1982.93 3418.98,1918.02 CN16.3@3418.98,1911.47
  Bottom Layer w24: L54.2@3330.39,2115.28 3330.39,2047.61 3343,2035 3343,2012.18 C180.1@3354.07,2001.11
NetC180_2: C180.2 R151.2 | length 55.9
  Bottom Layer w20: C180.2@3409.13,2001.11 3409.07,2050.07 R151.2@3414,2055
NetC181_1: C181.1 CN16.1 L55.2 | length 221.7
  Bottom Layer w24: CN16.1@3340.24,1832.73 3340.24,1769.26 3348.5,1761 3348.5,1709.5 3381.28,1676.72 L55.2@3381.28,1628
NetC181_2: C181.2 R152.2 | length 89
  Bottom Layer w20: 3413,1729 3435,1707 R152.2@3435,1685
  Bottom Layer w24: C181.2@3403.5,1761 3413,1751.5 3413,1729
NetC183_1: C183.1 U14.41 | length 64.6
  Top Layer w5: U14.41@2902.86,1861 2906.86,1865 2946,1865 C183.1@2960,1851
NetC184_1: C184.1 U14.42 | length 65.3
  Top Layer w5: U14.42@2902.86,1880.68 2908.54,1875 2946,1875 C184.1@2960,1889
NetC185_1: C185.1 U14.32 | length 90.9
  Top Layer w7: C185.1@2778.21,1680.21 2782.79,1680.21 2783,1680 2785,1682 2785,1697 2802,1714 2802,1740 2798.53,1743.47 U14.32@2798.53,1756.67
NetC186_1: C186.1 C213.1 L60.1 U14.3 U14.17 | length 455.1
  Top Layer w5: U14.3@2837.9,2024.39 2837.9,2039.9 2852,2054 v1(2852,2058)
  Top Layer w8: v1(2614,1920) 2614.47,1919.53 2635.14,1919.53 U14.17@2635.14,1920.06
  Bottom Layer w13.78: v1(2852,2058) 2853,2059 C186.1@2853,2081
  Bottom Layer w15: L60.1@2592,1957 L60.1@2592,1953 ; v1(2614,1920) 2593,1920 2592,1919 L60.1@2592,1953 ; v1(2852,2058) 2852,2047 2826,2021 2736,2021 2718,2003 2642,2003 L60.1@2592,1953
NetC189_1: C189.1 C190.1 C191.1 L61.1 U14.7 U14.20 U14.29 | length 653.9
  Top Layer w5: U14.29@2739.47,1756.67 2739.47,1734.53 v1(2740,1734)
  Top Layer w8: v1(2613,1861) 2613.53,1860.47 2635.14,1860.47 U14.20@2635.14,1861 ; v1(2745,2054) 2746,2054 2759.16,2040.84 U14.7@2759.16,2024.39 U14.7@2759.16,2023.86
  MidLayer1 w15.75: v1(2613,1861) 2641,1889 2689,1889 2709,1909 2709,1994 2745,2030 v1(2745,2054)
  Bottom Layer w5: C189.1@2720,1751 2723,1751 v1(2740,1734)
  Bottom Layer w15: C190.1@2593,1879 2593,1859 ; L61.1@2594,1840 2593,1841 2593,1859 ; v1(2613,1861) 2595,1861 2593,1859
  Bottom Layer w15.75: C191.1@2725,2064 2735,2064 v1(2745,2054)
  Bottom Layer w19.29: v1(2613,1861) 2624,1850 2625,1850 ; 2710,1764 C189.1@2723,1751
  Bottom Layer w20: 2625,1850 2644,1831 2692,1831 2710,1813 2710,1764
NetC194_1: C194.1 C195.1 C196.1 C197.1 C198.1 C199.1 L62.1 U14.31 U14.36 U14.40 | length 537.9
  Top Layer w5: U14.31@2778.84,1756.67 2778.84,1733.16 v1(2779,1733)
  Top Layer w6.5: U14.36@2877.27,1756.67 2893.33,1756.67 v1(2895,1755) ; U14.40@2902.86,1841.31 2927.68,1841.32 2946,1823 v1(2946,1809)
  Bottom Layer w6.5: C195.1@2912,1725 2895,1742 v1(2895,1755) 2901,1761 C197.1@2912,1761
  Bottom Layer w10: v1@2946,1801.5 v1(2946,1809)
  Bottom Layer w13.78: L62.1@2727,1705 2752.5,1705 C199.1@2761,1696.5 ; C199.1@2761.5,1696 C199.1@2761,1696.5 ; C199.1@2772,1699.5 C199.1@2770,1699.5 ; C197.1@2922.5,1774 2921.03,1775.47 C197.1@2921.03,1776.03 ; C194.1@2924,1820 2946.04,1809.09 2946.22,1809 v1(2946,1809) ; C199.1@2761,1696.5 2764,1699.5 C199.1@2770,1699.5 ; C199.1@2770,1699.5 2779,1708.5 v1(2779,1733) 2804,1733 2814,1723 2858.5,1723 2862,1719.5 2865,1719.5 C198.1@2865,1719.56 2865,1722.5 2867.5,1725 2912,1725 2912,1761 2909,1764 C197.1@2921.03,1776.03 ; C197.1@2921.03,1776.03 2921.08,1776.08 2922.48,1774.03 C197.1@2921.03,1776.03
  Bottom Layer w15: C197.1@2922.5,1774 2924,1775.5 C194.1@2924,1820
NetC202_1: C202.1 R165.2 R182.2 U14.30 | length 399.1
  Top Layer w5: R165.2@2641,1513 2674,1513 C202.1@2696,1535 ; R182.2@2704,1471 2711,1471 2712,1472 2712,1519 C202.1@2696,1535 ; U14.30@2759.16,1756.67 2759.16,1728.16 2739.5,1708.5 2739.5,1654.5 2747,1647 2747,1620.5 2739.5,1613 2739.5,1573.5 2701,1535 C202.1@2696,1535
NetC203_1: C203.1 C206.1 L63.1 U14.45 | length 225.2
  Top Layer w9: U14.45@2902.86,1939.74 2928.26,1939.74 v1(2931,1937)
  Bottom Layer w12: v1(2931,1937) 2951,1937 C206.1@2961,1947 ; 2967.5,1968 2967.5,1953.5 C206.1@2961,1947 ; C203.1@2967.5,1994 L63.1@2967.5,2031.5 ; L63.1@2977,2041 L63.1@2967.5,2031.5 ; C206.1@2961,1947 2961,2025 L63.1@2967.5,2031.5
NetC207_1: C207.1 U14.33 | length 67.5
  Top Layer w8: U14.33@2818.21,1756.67 2818.21,1692.1 C207.1@2820.32,1690
NetC207_2: C207.2 R153.1 | length 56.3
  Top Layer w8: R153.1@2820.32,1650 2820.32,1650.63 C207.2@2859.69,1690
NetCN1_70: CN1.70 R1.2 | length 57.9
  Top Layer w12: v1(676,1833) 679,1836 R1.2@710,1836
  Bottom Layer w12: v1(676,1833) 676.83,1832.17 CN1.70@698.27,1832.17
NetCN1_71: CN1.71 R1.1 | length 59
  Top Layer w12: v1(676,1882) 703.68,1882 R1.1@710,1875.68
  Bottom Layer w12: v1(676,1882) 676.17,1882.17 CN1.71@698.27,1882.17
NetCN6_2: CN6.2 L6.4 | length 240.5
  Bottom Layer w5: L6.4@1624.91,507.02 1641.02,507.02 1656,522 1667,522 1685,504 1805,504 1837.37,471.63 CN6.2@1837.37,470.63
NetCN6_4: CN6.4 L6.1 | length 246.7
  Bottom Layer w5: L6.1@1624.98,544.98 1643.02,544.98 1656,532 1672,532 1690,514 1789,514 1797,522 1797,537 1784.63,549.37 CN6.4@1758.63,549.37
NetCN8_2: CN8.2 L16.4 | length 241.2
  Bottom Layer w5: L16.4@3210.91,512.02 3224.88,526 3272,526 3293,505 3389,505 CN8.2@3423.37,470.63
NetCN8_4: CN8.4 L16.1 | length 249.4
  Bottom Layer w5: L16.1@3210.98,549.98 3222.96,538 ; 3223,538 3225,536 3277,536 3298,515 3375,515 3382,522 3382,543 3375.63,549.37 CN8.4@3344.63,549.37
NetCN10_2: CN10.2 L26.4 | length 243.1
  Bottom Layer w5: L26.4@1620.91,1191.02 1633.88,1204 1685,1204 1703,1186 1804,1186 CN10.2@1837.37,1152.63
NetCN10_4: CN10.4 L26.1 | length 251.5
  Bottom Layer w5: L26.1@1620.98,1228.98 1635.96,1214 1690,1214 1708,1196 1787,1196 1797,1206 1797,1221 1786.63,1231.37 CN10.4@1758.63,1231.37
NetCN12_2: CN12.2 L36.4 | length 248.4
  Bottom Layer w5: L36.4@3204.91,1197.02 3218.88,1211 3274,1211 3298,1187 3389,1187 CN12.2@3423.37,1152.63
NetCN12_4: CN12.4 L36.1 | length 261.7
  Bottom Layer w5: L36.1@3204.98,1234.98 3218.96,1221 3279,1221 3303,1197 3380,1197 3386,1203 3386,1219 3373.63,1231.37 CN12.4@3344.63,1231.37
NetCN14_2: CN14.2 L46.4 | length 240.6
  Bottom Layer w5: L46.4@1624.91,1872.02 1638.88,1886 1662,1886 1681,1867 1803.39,1867 CN14.2@1837.64,1832.76
NetCN14_4: CN14.4 L46.1 | length 245.4
  Bottom Layer w5: L46.1@1624.98,1909.98 1638.96,1896 1667,1896 1686,1877 1787,1877 1796,1886 1796,1902 1786.5,1911.5 CN14.4@1758.9,1911.5
NetCN16_2: CN16.2 L56.4 | length 237.9
  Bottom Layer w5: L56.4@3201.91,1851.02 3213.02,1851.02 3227,1865 3311,1865 3313,1867 3378,1867 3412.27,1832.73 CN16.2@3418.98,1832.73
NetCN16_4: CN16.4 L56.1 | length 242.3
  Bottom Layer w5: L56.1@3201.98,1888.98 3214.02,1888.98 3228,1875 3306,1875 3308,1877 3366,1877 3378,1889 3378,1902 3368.53,1911.47 CN16.4@3340.24,1911.47
NetL2_1: L2.1 U7.2 | length 95.7
  Top Layer w8: U7.2@3543.61,2481.43 3543.61,2430.24 3574.39,2399.47 L2.1@3575.11,2398.75
NetL3_1: L3.1 U8.2 | length 105.8
  Top Layer w9.84: 3874.32,2444.02 U8.2@3874.32,2477.49
  Top Layer w13.78: 3874.32,2444.02 L3.1@3925.5,2392.84
NetL4_2: L4.2 R23.1 | length 103.2
  Bottom Layer w23: R23.1@1580,779 1616.72,779 1651.72,744 L4.2@1663.72,756
NetL5_2: L5.2 R24.1 | length 86.6
  Bottom Layer w23: R24.1@1592,274 1668.72,274 L5.2@1675.72,267
NetL8_1: L8.1 R25.1 R26.1 | length 206.2
  Bottom Layer w25: R26.1@2196,300.5 2231.78,336.28 L8.1@2300,336.28 ; R25.1@2300,402 L8.1@2300,336.28 ; L8.1@2300,336.28 2300,328.28 2304,332.28 L8.1@2304,336 2304,336.28 L8.1@2300,336.28
NetL8_2: L8.2 L9.1 R26.2 R27.1 | length 1133.2
  Top Layer w17.72: 2297.98,171.94 2303.89,171.94 2318.94,171.94 2318.94,179.94 v1(2319.5,180.5)
  Top Layer w19.29: L9.1@2289.98,165.94 2290.48,166.44 2303.89,179.84 2305.55,181.5 ; v1(2321.5,202.5) v1@2322,203 ; 2326,168 2326,172 2331,172 2328,175 2325,175 v1(2319.5,180.5) ; v1@2338,184 2332,184 ; v1@2353,183 v1@2345,183 ; 2305.55,181.5 2306.05,182 v1@2321,182 ; 2305.55,181.5 2304.55,181.5 2303.89,180.84 2289.98,166.94 2289.98,191.98 2311,213 2320,213 v1@2326,207 ; 2305.55,181.5 v1@2319.5,181.5 ; v1(2319.5,180.5) v1@2319.5,181.5 ; v1(2319.5,180.5) v1@2320,181 ; v1@2319.5,181.5 v1@2320.5,181.5 ; v1@2320,181 2329,181 2329.5,181.5 ; v1@2320,181 v1@2320.5,181.5 ; v1@2320.5,181.5 v1@2321,182 ; v1@2320.5,181.5 2329.5,181.5 ; v1@2321,182 2330,182 ; v1@2322,203 v1@2330,203 ; v1@2322,203 v1@2323,204 ; v1@2323,204 v1@2329,204 ; v1@2323,204 v1@2326,207 ; v1@2326,207 v1@2329,204 ; v1@2329,204 2331,204 2332,203 ; v1@2329,204 v1@2330,203 ; 2329.5,181.5 v1(2343.5,181.5) ; 2329.5,181.5 2330,182 ; 2330,182 2331,183 ; 2330,182 2343,182 v1(2343.5,181.5) ; v1@2330,203 2332,203 ; 2331,183 2331,184 2332,184 ; 2331,183 v1@2345,183 ; 2332,184 2332,203 ; 2332,203 v1@2343.5,203 ; v1(2343.5,181.5) v1@2344,182 ; v1(2343.5,181.5) v1@2351.5,181.5 ; v1(2343.5,202.5) v1@2343.5,203 ; v1(2343.5,202.5) 2349.5,202.5 v1@2350,203 ; v1(2343.5,202.5) v1@2344,203 ; v1@2343.5,203 v1@2344,203 ; v1@2344,182 v1@2345,183 ; v1@2344,182 v1@2352,182 ; v1@2344,203 2345,204 v1@2351,204 ; v1@2344,203 v1@2350,203 ; v1@2350,203 v1@2351,204 ; v1@2350,203 2354,203 v1@2353,204 ; v1@2351,204 v1@2353,204 ; v1@2351.5,181.5 v1@2352,182 ; v1@2351.5,181.5 v1(2366.5,181.5) ; v1@2352,182 2366,182 v1(2366.5,181.5) ; v1@2353,204 2365,204 v1(2366.5,202.5) 2374,195 2374,183 2368,183 v1(2366.5,181.5)
  Top Layer w20: v1(2321.5,202.5) 2303.89,184.89 2303.89,180.84 2303.89,179.84 2303.89,171.94 2303.89,168 2326,168
  Bottom Layer w19.29: R27.1@2289,178.5 v1@2319.5,178.5 ; 2295,202.5 v1(2321.5,202.5) ; L8.2@2304,233.72 v1@2334.72,203 ; v1(2366.5,181.5) 2368,183 2374,183 2374,195 v1(2366.5,202.5) 2365,204 v1@2353,204 ; v1@2367,183 v1@2353,183 ; v1@2372.5,178.5 2353,178.5 ; v1@2319.5,178.5 v1(2319.5,180.5) 2320,181 v1@2328.5,181 ; v1@2319.5,178.5 2331,178.5 ; v1(2321.5,202.5) 2323,204 2331,204 2332,203 v1@2334.72,203 ; v1(2321.5,202.5) v1@2335.22,202.5 ; v1@2328.5,181 2329,181 2331,183 ; v1@2328.5,181 2331,178.5 ; 2331,178.5 2353,178.5 ; 2331,183 2331,200.72 2337,200.72 v1@2335.22,202.5 ; 2331,183 v1@2345,183 ; v1@2334.72,203 v1@2335.22,202.5 ; v1@2334.72,203 v1@2344,203 ; v1@2335.22,202.5 v1(2343.5,202.5) ; v1(2343.5,202.5) 2349.5,202.5 v1@2350,203 ; v1(2343.5,202.5) v1@2344,203 ; v1@2344,203 2345,204 v1@2351,204 ; v1@2344,203 v1@2350,203 ; v1@2345,183 v1(2343.5,181.5) 2345.5,179.5 2352,179.5 2353,178.5 ; v1@2345,183 v1@2353,183 ; v1@2350,203 v1@2351,204 ; v1@2350,203 v1@2353,203 ; v1@2351,204 v1@2353,204 ; v1@2353,183 v1@2353,203 ; v1@2353,203 2354,203 v1@2353,204
  Bottom Layer w20: R27.1@2289,177.5 R27.1@2289,177.56 2289,178.5 2289,208.5 ; 2295,202.5 2289,208.5 ; L8.2@2304,231.72 2304,233.72 2304,245.72 2289,230.72 2289,208.5
  Bottom Layer w24: R26.2@2196,245.5 2292.22,245.5 2292.45,245.72 L8.2@2304,245.72
NetL14_2: L14.2 R50.1 | length 101
  Bottom Layer w23: R50.1@3167,773 R50.1@3167,766.53 3245.2,766.53 L14.2@3256.72,755
NetL15_2: L15.2 R51.1 | length 108.1
  Bottom Layer w20: R51.1@3174,337 3240,271 L15.2@3254.72,271
NetL18_1: L18.1 R52.1 R53.1 | length 170.8
  Bottom Layer w20: R52.1@3885,396 3885,339.5 R53.1@3886,338.5
  Bottom Layer w24: L18.1@3778,330.28 3827.28,330.28 3839,342 3882.5,342 R53.1@3885,339.5
NetL18_2: L18.2 L19.1 R53.2 R54.1 | length 707.6
  Top Layer w17.72: L19.1@3671.98,174.94 3678.92,168 3680.89,168 v1(3703,168) ; 3687,138 3693,144 v1(3703,144)
  Top Layer w19.29: v1@3697.89,191 v1(3703,191) v1(3726,191) v1(3726,168) ; v1(3703,168) v1(3726,168) ; v1@3703.89,145 v1(3726,145) v1(3726,168)
  Top Layer w19.68: v1@3697.89,191 3677.89,171 3680.89,168 v1@3703.89,145
  Bottom Layer w19.29: R54.1@3703,118.5 v1(3703,144) v1(3703,168) v1(3703,191) ; R54.1@3712.5,109 3726,122.5 v1(3726,145) v1(3726,168) v1(3726,191) 3726,227.45
  Bottom Layer w25: R54.1@3703,118.5 R54.1@3712.5,109 ; v1(3703,191) 3703,229 3713.72,239.72 ; 3726,227.45 3713.72,239.72 ; R53.2@3886,283.5 3842.22,239.72 3713.72,239.72
NetL24_2: L24.2 R74.1 | length 97.4
  Bottom Layer w10: 1639.72,1462 L24.2@1667.72,1434
  Bottom Layer w19.29: R74.1@1589,1479 1622.72,1479 1639.72,1462
NetL25_2: L25.2 R75.1 | length 76.2
  Bottom Layer w25: R75.1@1585,953 1652.72,953 L25.2@1658.72,947
NetL28_1: L28.1 R76.1 R77.1 | length 186.1
  Bottom Layer w23: R77.1@2193,977.5 2235.78,1020.28 2299,1020.28 2295,1024.28 R76.1@2295,1081
NetL28_2: L28.2 L29.1 R77.2 R78.1 | length 789.9
  Top Layer w5: 2303.89,862 v1@2316,862 ; v1(2362,886) 2354,878 2354,865 2354,862 v1@2317.5,862 ; v1@2316,862 v1(2316,863.5) v1@2317.5,862 ; v1@2316,862 v1@2317.5,862
  Top Layer w17.72: 2297.98,865.94 2305.77,873.73 2316.27,884.23 v1@2318.05,886 ; v1(2314.5,886) v1@2318.05,886 ; 2327.89,886 v1@2318.05,886
  Top Layer w19.29: L29.1@2285.98,865.94 2306.05,886 v1(2314.5,886) 2316.27,884.23 v1@2321.19,879.31 ; 2303.89,862 2305.89,864 ; v1@2346,886 v1(2338,886) ; v1@2353,864 2352.5,864.5 v1@2345.5,864.5 ; v1@2354,865 2338.5,865 v1(2338,864.5) ; 2354,878 2354,879 2345,879 v1(2338,886) ; v1@2354,886 2353.5,886.5 2338.5,886.5 v1(2338,886) ; v1@2362.5,864 v1(2362,864.5) v1@2362.5,865 ; 2305.89,864 v1@2315.5,864 ; 2305.89,864 v1@2310.69,868.81 ; v1@2310.69,868.81 v1@2315.5,864 ; v1@2310.69,868.81 v1@2321.19,879.31 ; v1@2315.5,864 v1(2316,863.5) ; v1@2315.5,864 v1@2316,864 ; v1(2316,863.5) v1@2316,864 ; v1(2316,863.5) v1@2316.5,864 ; v1@2316,864 v1@2316.5,864 ; v1@2316.5,864 v1@2338.5,864 ; v1@2321.19,879.31 2327.89,886 v1(2338,886) ; v1(2338,864.5) v1@2345.5,864.5 ; v1(2338,864.5) v1@2338.5,864 ; v1@2338.5,864 2346,864 v1@2345.5,864.5
  Top Layer w20: 2294,914 2294,907.5 2307,894.5 2307,886.95 v1@2306.05,886
  Bottom Layer w19.29: R78.1@2283,870.5 v1@2316,870.5 ; R78.1@2298.5,886 v1(2314.5,886) v1(2338,886) v1(2362,886) v1@2370,886 ; v1@2316,870.5 v1(2316,863.5) 2323,870.5 ; v1@2316,870.5 2323,870.5 ; 2323,870.5 v1@2332,870.5 ; v1@2332,870.5 v1(2338,864.5) ; v1@2332,870.5 v1@2338,870.5 ; v1(2338,864.5) v1@2338,870.5 ; v1(2338,864.5) v1@2344,870.5 ; v1@2338,870.5 v1@2344,870.5 ; v1@2344,870.5 v1@2362,870.5 ; v1@2362,870.5 v1(2362,864.5) 2363,865.5 2370.5,865.5 2370.5,870.5 v1@2362,870.5
  Bottom Layer w23: R77.2@2193,922.5 2200.22,929.72 2299,929.72 2283,913.72 R78.1@2283,870.56 R78.1@2283,870.5
  Bottom Layer w25: R78.1@2283,870.5 R78.1@2298.5,886
NetL34_1: L34.1 R98.1 | length 100.9
  Bottom Layer w30: R98.1@3169,1454.53 R98.1@3169,1461 ; R98.1@3169.28,1449 L34.1@3258,1449 ; L34.1@3257.72,1433 L34.1@3261.72,1429
NetL35_1: L35.1 R99.1 | length 95.4
  Bottom Layer w25: R99.1@3156,959 3228.72,959 L35.1@3244.72,943
NetL38_1: L38.1 L39.2 R100.2 R102.1 | length 786.9
  Top Layer w19.29: v1@3701.89,829 v1(3727,829) v1(3727,852) ; v1(3704,828) 3696,828 3691,823 3691,837.92 L38.1@3676.92,852 ; L38.1@3676.92,852 3678.89,852 3691,852 ; L38.1@3676.92,852 3671.98,856.94 3690.05,875 v1(3704,875) ; 3691,852 v1(3704,852) v1(3727,852) ; 3691,852 3691,862 v1(3704,875) ; v1(3704,875) v1(3727,875) v1(3727,852)
  Top Layer w19.68: L38.1@3677.89,853 3678.89,852 v1@3701.89,829
  Bottom Layer w19.29: R102.1@3704,789.5 v1(3704,828) v1(3704,852) v1(3704,875) 3704,898
  Bottom Layer w19.68: R102.1@3704,789.5 3716.5,777 3727,787.5 v1(3727,829) v1(3727,852) v1(3727,875) 3727,905 L39.2@3734.72,912.72 ; 3704,898 3718.72,912.72 L39.2@3734.72,912.72 ; R100.2@3891,964.5 3839.22,912.72 L39.2@3734.72,912.72
NetL39_1: L39.1 R100.1 R101.1 | length 179.9
  Bottom Layer w19.68: L39.1@3782,1003.28 3785.72,1007 3835,1007 3847.5,1019.5 3891,1019.5 R100.1@3891,1019.56 3891,1071 R101.1@3882,1080
NetL44_1: L44.1 R122.1 | length 113.7
  Bottom Layer w23: R122.1@1581,2113 R122.1@1582,2113 ; R122.1@1582,2129 R122.1@1582,2122.53 R122.1@1582,2113 ; L44.1@1656.72,2135 1656.72,2113 R122.1@1582,2113
NetL45_1: L45.1 R123.1 | length 80.6
  Bottom Layer w25: R123.1@1587,1633 1664.72,1633 L45.1@1666.72,1631
NetL48_1: L48.1 R124.1 R125.1 | length 183
  Bottom Layer w20: R125.1@2181,1684.5 2226.5,1684.5 2239.28,1697.28 2294,1697.28 R124.1@2294,1762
